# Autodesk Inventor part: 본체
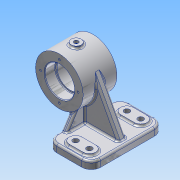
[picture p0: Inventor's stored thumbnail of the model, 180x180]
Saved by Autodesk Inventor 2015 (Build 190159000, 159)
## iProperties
Created: 2023-08
Part Number: 본체
Material: 알루미늄 6061
Document SubType Name: Modeling
Designer: 학생용
Mass: 777.816 g
Surface Area: 536.641 cm^2
Volume: 288.08 cm^3
Density: 2.7 g/cm^3
Appearance: 알루미늄 - 평지
Author: 학생용
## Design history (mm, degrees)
sketch "스케치1"
  geometry: L1 (0, 0)-(54, 0); L2 (0, 23.5)-(0, 38); L3 (0, 38)-(54, 38); L4 (54, 38)-(54, 23.5); L5 (54, 23.5)-(37, 23.5); L6 (37, 23.5)-(37, 20.5); L7 (37, 20.5)-(17, 20.5); L8 (17, 20.5)-(17, 23.5); L9 (17, 23.5)-(0, 23.5)
  constraints: 18 end point, 5 perpendicular, 4 point on line, 2 horizontal, 1 vertical
  dimensions: "d0" = 54 distance of L1.start L1.end; "d1" = 17 distance between parallel lines of L8 L2; "d2" = 17 distance between parallel lines of L4 L6; "d3" = 41 diameter of L7 L1; "d4" = 47 diameter of L5 L1; "d5" = 76 diameter of L3 L1
revolve "회전1" sketch "스케치1" stored, may be unused: angle "d6" = 90 deg
chamfer "모따기1" distance "d7" = 1; stored, may be unused: second distance "d8" = 2, angle "d9" = 45 deg
fillet "모깎기1" dims "d10" = 1
node "작업 평면1"
sketch "스케치3"
  geometry: L1 (-38, 0)-(-38, 54) reference; L2 (0, 27)-(82, 27); L3 (38, 54)-(-38, 54) reference; L4 (0, 54)-(0, 27); L5 (82, -31)-(12, -31); L6 (12, -31)-(12, 85); L7 (12, 85)-(82, 85); L8 (82, 85)-(82, -31); 2 further points
  constraints: 12 end point, 3 midpoint, 2 horizontal, 2 parallel, 2 perpendicular, 1 coincident
  dimensions: "d20" = 82 distance of L2.start L2.end; "d21" = 27 distance from line of L2.start L3; "d24" = 116 distance of L7.end L5.start; "d25" = 70 distance of L6.end L7.end
extrude "돌출1" join sketch "스케치3" distance "d26" = 12; taper "d27" = 0 deg
node "작업 평면2"
sketch "스케치7"
  geometry: L1 (40, -14)-(62, -14); L2 (40, -24)-(62, -24); L3 (62, -4)-(40, -4); L4 (40, 68)-(62, 68); L5 (40, 58)-(62, 58); L6 (62, 78)-(40, 78); L7 (-38, 0)-(-38, 54) reference; L8 (-38, 27)-(-55.074, 27); L9 (82, -31)-(82, 85) reference; A1 r 10 centre (40, -14) between (40, -4) and (40, -24); A2 r 10 centre (62, -14) between (62, -24) and (62, -4); A3 r 10 centre (40, 68) between (40, 78) and (40, 58); A4 r 10 centre (62, 68) between (62, 58) and (62, 78); 3 further points
  constraints: 18 end point, 8 point on circle, 8 tangent, 4 centre point, 3 midpoint, 3 parallel, 2 horizontal
  dimensions: "d51" = 82 distance of L1.end L4.end; "d52" = 41 distance from line of point (51, 68) L8; "d53" = 10 radius of A2; "d54" = 10 radius of A4; "d56" = 20 distance from line of L9 L1.end; "d57" = 20 distance from line of L9 L4.end; "d58" = 22 distance of L1.start L1.end; "d59" = 22 distance of L4.start L4.end
extrude "돌출2" join sketch "스케치7" distance "d60" = 3; taper "d61" = 0 deg
sketch "스케치8"
  geometry: C1 r 4.5 at (40, -14); C2 r 4.5 at (62, -14); C3 r 4.5 at (62, 68); C4 r 4.5 at (40, 68); A1 r 10 centre (40, -14) between (40, -4) and (40, -24) reference; A2 r 10 centre (62, -14) between (62, -24) and (62, -4) reference; A3 r 10 centre (62, 68) between (62, 58) and (62, 78) reference; A4 r 10 centre (40, 68) between (40, 78) and (40, 58) reference; 1 further point
  constraints: 4 centre point, 4 coincident
  dimensions: "d62" = 9 diameter of C4; "d63" = 9 diameter of C3; "d64" = 9 diameter of C2; "d65" = 9 diameter of C1
extrude "돌출3" cut sketch "스케치8" stored distance "d66" = 3; taper "d67" = 0 deg
sketch "스케치9"
  geometry: A1 r 30 centre (0, 0) between (0, 30) and (-30, 0); 3 further points
  constraints: 4 point on circle, 2 horizontal alignment, 2 vertical alignment, 1 centre point, 1 coincident
  dimensions: "d68" = 60 diameter of A1
hole "구멍2" sketch "스케치9" at (0, 30), (-30, 0), (0, -30), (30, 0) diameter "d69" = 3.242; stored, may be unused: countersink angle "d73" = 82 deg, drill point angle "d75" = 118 deg; dims "d70" = 8, "d71" = 3.023, "d72" = 2, "d74" = 10
sketch "스케치10"
  geometry: C1 r 30 at (0, 0); C2 r 1.621 at (0, -30) reference; C3 r 1.621 at (30, 0) reference; C4 r 1.621 at (0, 30) reference; C5 r 1.621 at (-30, 0) reference; 5 further points
  constraints: 5 coincident, 1 centre point
  dimensions: "d76" = 60 diameter of C1
hole "구멍3" sketch "스케치10" at (0, -30), (30, 0), (0, 30), (-30, 0) diameter "d77" = 3.242; stored, may be unused: countersink angle "d81" = 82 deg, drill point angle "d83" = 118 deg; dims "d78" = 8, "d79" = 3.023, "d80" = 2, "d82" = 10
node "작업 평면3"
sketch "스케치11"
  geometry: L1 (38, 54)-(-38, 54) reference; C1 r 8 at (0, 27); 1 further point
  constraints: 1 centre point, 1 vertical alignment
  dimensions: "d85" = 27 distance from line of C1.centre L1; "d86" = 16 diameter of C1
extrude "돌출4" join sketch "스케치11" stored distance "d87" = 3; taper "d88" = 0 deg
sketch "스케치12"
  geometry: L1 (38, 27)-(-38, 27) reference; C1 r 3.5 at (0, 0); 1 further point
  constraints: 1 centre point, 1 vertical alignment
  dimensions: "d89" = 7 diameter of C1; "d90" = 27 distance from line of C1.centre L1
extrude "돌출5" cut sketch "스케치12" distance "d91" = 4; taper "d92" = 0 deg
sketch "스케치13"
  geometry: L1 (38, 27)-(-38, 27) reference; 2 further points
  constraints: 1 vertical alignment
  dimensions: "d93" = 27 distance from line of L1 point (0, 0)
hole "구멍4" sketch "스케치13" at (0, 0) diameter "d94" = 5.188; stored, may be unused: countersink angle "d98" = 82 deg, drill point angle "d100" = 118 deg; dims "d95" = 12, "d96" = 3.023, "d97" = 2, "d99" = 16
node "작업 평면4"
sketch "스케치15"
  geometry: L1 (89.033, 48)-(86.621, 48) reference; L2 (86.621, 48)-(86.621, 68) reference; L3 (86.621, 68)-(89.033, 68) reference; L4 (90.205, 69)-(90.205, 84) reference; L5 (91.36, 85)-(106.056, 85) reference; L6 (106.056, 85)-(106.056, 31) reference; L7 (106.056, 31)-(91.36, 31) reference; L8 (90.205, 32)-(90.205, 47) reference; L9 (49.795, 47)-(49.795, 32) reference; L10 (48.64, 31)-(33.944, 31) reference; L11 (33.944, 31)-(33.944, 85) reference; L12 (33.944, 85)-(48.64, 85) reference; L13 (49.795, 84)-(49.795, 69) reference; L14 (50.967, 68)-(53.379, 68) reference; L15 (53.379, 68)-(53.379, 48) reference; L16 (53.379, 48)-(50.967, 48) reference; L17 (0, 116)-(12, 116) reference; L18 (12, 116)-(12, 0) reference; L19 (12, 0)-(0, 0) reference; L20 (0, 0)-(0, 116) reference; L21 (12, 0)-(12, 116) reference; L22 (12, 94)-(40.238, 75.662); L23 (40.238, 75.662)-(40.238, 40.338); L24 (40.238, 40.338)-(12, 22); 1 further point
  constraints: 6 end point, 2 point on line, 1 parallel, 8 other
  dimensions: "d102" = 22 distance from line of L17 L22.start; "d103" = 33 deg angle of L17 L22; "d104" = 33 deg angle of L19 L24; "d105" = 22 distance from line of L19 L24.end
extrude "돌출6" join sketch "스케치15" distance "d106" = 8; taper "d107" = 0 deg
sketch "스케치16"
  geometry: L1 (70, 0)-(70, 12) reference; L2 (70, 12)-(0, 12) reference; L3 (21.529, 87.882)-(62, 12); 2 further points
  constraints: 2 end point, 1 point on line, 3 other
  dimensions: "d108" = 8 distance from line of L1 L3.end
feature "리브3" sketch "스케치16" dims "d109" = 1, "d110" = 12, "d111" = 0, "d112" = 0, "d113" = 1, "d114" = 1
fillet "모깎기4" dims "d115" = 3
fillet "모깎기5" dims "d116" = 3
fillet "모깎기6" dims "d117" = 3
fillet "모깎기7" dims "d118" = 3
fillet "모깎기9" dims "d120" = 3
fillet "모깎기10" dims "d121" = 15
fillet "모깎기11" dims "d122" = 3
fillet "모깎기12" dims "d123" = 3
fillet "모깎기13" dims "d124" = 3
fillet "모깎기14" dims "d125" = 3
sketch "스케치17"
  geometry: L1 (-30, 63.734)-(-30, -22.266) reference; L2 (81, 24.234)-(81, 17.234) reference; L3 (81, 20.734)-(90.805, 20.734); L4 (81, 28.734)-(81, 12.734) reference; 3 further points
  constraints: 2 end point, 2 midpoint, 1 horizontal, 1 horizontal alignment, 1 other
  dimensions: "d126" = 19 distance from line of L1 point (-11, 20.734)
extrude "돌출7" join sketch "스케치17" distance "d127" = 0.5; taper "d128" = 0 deg
node "솔리드1"
node "절단 모서리 투영3"
other parameters: "d84" = 41
